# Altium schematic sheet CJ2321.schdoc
size 127 x 101 mm
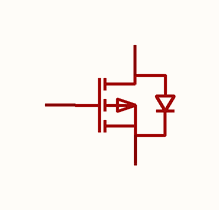
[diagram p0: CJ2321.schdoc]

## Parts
Q?  cj2321  [SOT-23-3_L2.9-W1.3-P1.90-LS2.4-BR]  (value not drawn)

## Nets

Not connected (* = marked no-connect by the designer): Q? 1(G) 2(S) 3(D)

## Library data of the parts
Q? = cj2321: 数量:1个P沟道;漏源电压(Vdss):20V;连续漏极电流(Id):2.9A;导通电阻(RDS(on)):110mΩ@1.8V;耗散功率(Pd):350mW;阈值电压(Vgs(th)):900mV;; Manufacturer: CJ(江苏长电/长晶); AddInBom: yes; ModelId: c62791f0466c4ae2a892c056b845b0ca; ModelName: SOT-23-3P_L2.9-W1.3-H1.0-LS2.4-P0.95; ModelTransform: 98.425,114.173,0,180,0,0,0.0005,-0.0005,0; Number: 1个P沟道; Drain to Source Voltage: 20V; Current - Continuous Drain(Id): 2.9A; Pd - Power Dissipation: 350mW; Gate Threshold Voltage (Vgs(th)): 900mV; Gate Charge(Qg): 13nC; Input Capacitance(Ciss): 715pF; Reverse Transfer Capacitance (Crss@Vds): 120pF; Type: P沟道; Output Capacitance(Coss): 170pF; Vgs: ±12V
